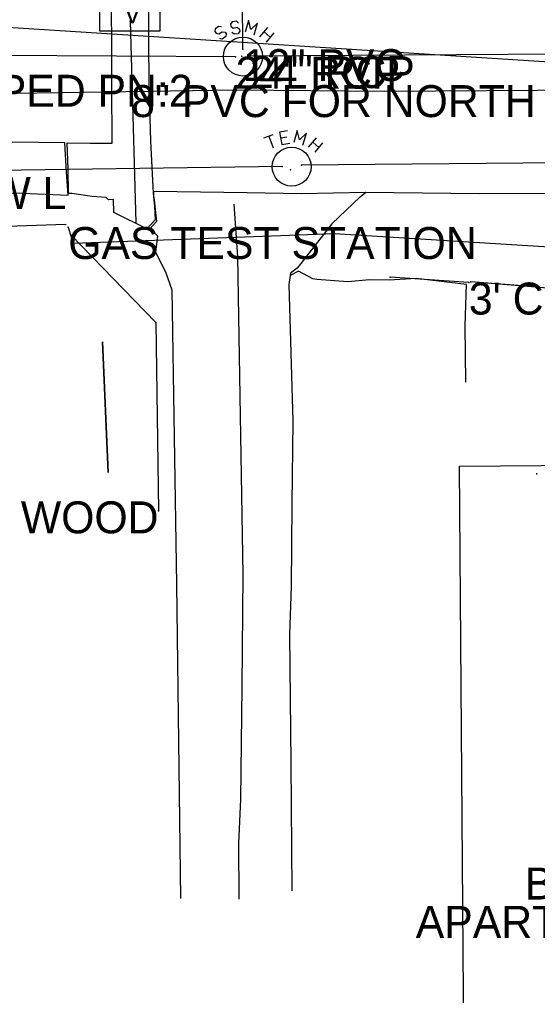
# Model space of a CAD drawing. Extents: x 1304270 to 1306561, y 1876019 to 1876752.
# Drawn here: x 1305592.5 to 1305673.5, y 1876265.9 to 1876418.6 of the extents above; entities that cross this region are included whole.
import ezdxf

# ---------------------------------------------------------------- set-up
doc = ezdxf.new("R2010")
doc.units = 0
for name, color, linetype in [('Default', 7, 'Continuous'), ('S_BUILDING', 7, 'Continuous'), ('S_BUILDING_ANNOT', 7, 'Continuous'), ('S_EDGE_CONCRETE', 7, 'Continuous'), ('S_EDGE_PAVEMENT', 7, 'Continuous'), ('S_ELECTRIC_UTILITIES_ANNOT', 7, 'Continuous'), ('S_FENCE', 7, 'Continuous'), ('S_FENCE_ANNOT', 7, 'Continuous'), ('S_FIBER_OPTIC_CABLE', 7, 'Continuous'), ('S_GAS_UTILITIES', 7, 'Continuous'), ('S_MISC_STRUCTURES_ANNOT', 7, 'Continuous'), ('S_MSC_PT_SYM', 7, 'Continuous'), ('S_PARKING', 7, 'Continuous'), ('S_PAVEMENT_CROWN', 7, 'Continuous'), ('S_PRIMARY_CTL_ANNOT', 7, 'Continuous'), ('S_SANITARY_SEWER', 7, 'Continuous'), ('S_SANITARY_SEWER_ANNOT', 7, 'Continuous'), ('S_STR_PT_SYM', 7, 'Continuous'), ('S_SURVEY_TEXT_ANNOT', 7, 'Continuous'), ('S_TELEPHONE_UTILITIES_ANNOT', 7, 'Continuous'), ('S_TREE', 7, 'Continuous'), ('S_UTL_PT_SYM', 7, 'Continuous'), ('S_WATER_UTILITIES', 7, 'Continuous')]:
    doc.layers.add(name, color=color, linetype=linetype)

msp = doc.modelspace()

# ---------------------------------------------------------------- linework, layer by layer
at = {"layer": 'Default'}
msp.add_line((1305473.53, 1876424.94), (1305993.25, 1876391.55), dxfattribs=at)
at = {"layer": 'S_BUILDING'}
msp.add_lwpolyline([(1305662.34, 1876217.81), (1305661.36, 1876348.7), (1305693.3, 1876348.94), (1305694.28, 1876218.05)], close=True, dxfattribs=at)
at = {"layer": 'S_EDGE_CONCRETE'}
for points in [[(1305600.18, 1876391.37), (1305600.11, 1876395.15), (1305599.99, 1876399.31), (1305603.58, 1876399.22), (1305607.04, 1876399.22), (1305606.97, 1876408.21), (1305606.95, 1876415.73), (1305606.84, 1876422.83)], [(1305612.7, 1876421.97), (1305612.68, 1876415.16), (1305612.77, 1876408.63), (1305613.02, 1876399.57), (1305613.37, 1876392.39), (1305613.42, 1876391.39), (1305613.66, 1876389.36), (1305613.74, 1876387.23), (1305612.42, 1876385.83), (1305607.29, 1876388.41), (1305607.23, 1876390.4), (1305606.42, 1876390.35), (1305606.05, 1876390.71), (1305603.89, 1876390.91), (1305600.7, 1876391.35)], [(1305587.07, 1876391.56), (1305592.92, 1876391.39), (1305600.11, 1876391.1), (1305599.86, 1876394.71), (1305599.63, 1876399.29), (1305591.28, 1876399.4), (1305587.25, 1876399.27), (1305587.19, 1876395.57), (1305587.04, 1876391.81)], [(1305600.7, 1876391.35), (1305600.18, 1876391.37)]]:
    msp.add_lwpolyline(points, dxfattribs=at)
at = {"layer": 'S_EDGE_PAVEMENT'}
for points in [[(1305613.53, 1876391.75), (1305628.13, 1876391.53), (1305636.57, 1876391.38), (1305646.7, 1876391.57), (1305664.4, 1876391.37), (1305677.09, 1876391.42), (1305689.77, 1876391.47), (1305705.71, 1876391.48), (1305716.06, 1876391.37), (1305738.42, 1876391.47), (1305752.22, 1876391.48), (1305766.03, 1876391.49), (1305779.83, 1876391.49), (1305793.63, 1876391.5), (1305816.58, 1876391.56), (1305839.54, 1876391.62), (1305862.15, 1876391.47), (1305884.77, 1876391.33), (1305898.76, 1876391.18), (1305901.73, 1876391.47), (1305913.59, 1876391.75), (1305924.92, 1876391.98), (1305934.98, 1876391.98)], [(1305613.54, 1876390.81), (1305613.53, 1876391.75)], [(1305645.8, 1876390.84), (1305646.7, 1876391.57)], [(1305613.54, 1876390.81), (1305613.95, 1876386.98), (1305612.91, 1876385.84), (1305613.43, 1876385.43), (1305614.1, 1876384.73), (1305613.77, 1876382.16), (1305615.36, 1876379.1), (1305616.36, 1876376.27), (1305616.71, 1876353.21), (1305617.06, 1876330.15), (1305617.38, 1876305.59), (1305617.7, 1876281.03)], [(1305645.8, 1876390.84), (1305641.39, 1876386.64), (1305635.93, 1876379.66), (1305634.93, 1876378.88), (1305634.67, 1876377.12), (1305635.26, 1876355.72), (1305635.13, 1876342.79), (1305635, 1876329.85), (1305634.78, 1876322.35), (1305634.95, 1876302.28), (1305635.12, 1876282.21)]]:
    msp.add_lwpolyline(points, dxfattribs=at)
at = {"layer": 'S_FENCE'}
for p, q in [((1305662.81, 1876377.42), (1305650.48, 1876378.27)), ((1305697.1, 1876374.76), (1305663.1, 1876377.56))]:
    msp.add_line(p, q, dxfattribs=at)
for points in [[(1305662.81, 1876377.42), (1305650.48, 1876378.27)], [(1305662.81, 1876377.42), (1305650.48, 1876378.27)], [(1305673.18, 1876376.73), (1305663.1, 1876377.56)], [(1305673.18, 1876376.73), (1305663.1, 1876377.56)]]:
    msp.add_lwpolyline(points, dxfattribs=at)
at = {"layer": 'S_FIBER_OPTIC_CABLE'}
for p, q in [((1305684.65, 1876396.24), (1305636.63, 1876395.82)), ((1305633.63, 1876395.59), (1305588.12, 1876394.97))]:
    msp.add_line(p, q, dxfattribs=at)
at = {"layer": 'S_GAS_UTILITIES'}
for p, q in [((1305599.74, 1876386.5), (1305541.16, 1876384.5)), ((1305600.99, 1876383.55), (1305600.25, 1876385.84)), ((1305600.56, 1876384.87), (1305613.85, 1876371.19)), ((1305641.77, 1876385.04), (1305600.99, 1876383.55)), ((1305681.24, 1876382.6), (1305641.77, 1876385.04)), ((1305613.85, 1876371.19), (1305614.27, 1876341.7))]:
    msp.add_line(p, q, dxfattribs=at)
at = {"layer": 'S_MSC_PT_SYM'}
for points in [[(1305609.97, 1876408.32), (1305609.97, 1876408.37), (1305609.97, 1876408.32), (1305609.92, 1876408.32), (1305609.97, 1876408.32), (1305609.97, 1876408.27), (1305609.97, 1876408.32), (1305610.02, 1876408.32)], [(1305600.14, 1876386.11), (1305600.14, 1876386.16), (1305600.14, 1876386.11), (1305600.09, 1876386.11), (1305600.14, 1876386.11), (1305600.14, 1876386.06), (1305600.14, 1876386.11), (1305600.19, 1876386.11)], [(1305650.48, 1876378.27), (1305650.48, 1876378.32), (1305650.48, 1876378.27), (1305650.43, 1876378.27), (1305650.48, 1876378.27), (1305650.48, 1876378.22), (1305650.48, 1876378.27), (1305650.53, 1876378.27)], [(1305662.81, 1876377.42), (1305662.81, 1876377.47), (1305662.81, 1876377.42), (1305662.76, 1876377.42), (1305662.81, 1876377.42), (1305662.81, 1876377.37), (1305662.81, 1876377.42), (1305662.86, 1876377.42)], [(1305663.1, 1876377.56), (1305663.1, 1876377.61), (1305663.1, 1876377.56), (1305663.05, 1876377.56), (1305663.1, 1876377.56), (1305663.1, 1876377.51), (1305663.1, 1876377.56), (1305663.15, 1876377.56)]]:
    msp.add_lwpolyline(points, dxfattribs=at)
at = {"layer": 'S_PARKING'}
msp.add_lwpolyline([(1305662.32, 1876361.82), (1305662.23, 1876370.65), (1305662.45, 1876377.11), (1305654.57, 1876378.06), (1305650.33, 1876377.81), (1305647.29, 1876377.87), (1305643.87, 1876377.56), (1305639.01, 1876377.9), (1305638.39, 1876378), (1305636.15, 1876379.23), (1305634.94, 1876378.6)], dxfattribs=at)
at = {"layer": 'S_PAVEMENT_CROWN'}
for points in [[(1305584.78, 1876406.94), (1305605.66, 1876407.25), (1305626.54, 1876407.56), (1305649.67, 1876407.38), (1305673.56, 1876407.51), (1305697.46, 1876407.64), (1305720.67, 1876407.97), (1305743.89, 1876408.29), (1305756.53, 1876408.46), (1305769.18, 1876408.63), (1305781.82, 1876408.79), (1305794.47, 1876408.96), (1305817.8, 1876409.07)], [(1305626.06, 1876389.71), (1305626.63, 1876381.43), (1305627.05, 1876356.58), (1305627.46, 1876331.74), (1305627.28, 1876314.17), (1305627.09, 1876296.6), (1305626.79, 1876289.63), (1305626.83, 1876280.91)]]:
    msp.add_lwpolyline(points, dxfattribs=at)
at = {"layer": 'S_SANITARY_SEWER'}
for p, q in [((1305627.46, 1876413.95), (1305625.83, 1876600.63)), ((1305623.69, 1876417.49), (1305623.15, 1876417.11)), ((1305624.11, 1876417.42), (1305623.69, 1876417.49)), ((1305623.15, 1876417.11), (1305623.07, 1876416.72)), ((1305623.07, 1876416.72), (1305623.26, 1876416.45)), ((1305623.26, 1876416.45), (1305623.69, 1876416.33)), ((1305623.69, 1876416.33), (1305624.23, 1876416.68)), ((1305624.23, 1876416.68), (1305624.7, 1876416.6)), ((1305624.77, 1876415.91), (1305624.23, 1876415.52)), ((1305624.7, 1876416.6), (1305624.85, 1876416.33)), ((1305624.85, 1876416.33), (1305624.77, 1876415.91)), ((1305630.12, 1876415.87), (1305631.36, 1876417.34)), ((1305630.78, 1876416.64), (1305631.75, 1876415.83)), ((1305632.33, 1876416.53), (1305631.09, 1876415.05)), ((1305624.23, 1876415.52), (1305623.84, 1876415.6)), ((1305931.77, 1876414.75), (1305628.57, 1876412.86)), ((1305626.32, 1876412.77), (1305348.54, 1876414.26))]:
    msp.add_line(p, q, dxfattribs=at)
for points in [[(1305626.79, 1876418.04), (1305626.44, 1876418.31), (1305625.78, 1876418.23), (1305625.55, 1876417.88), (1305625.59, 1876417.57), (1305625.94, 1876417.26), (1305626.56, 1876417.38), (1305626.94, 1876417.07), (1305626.98, 1876416.76), (1305626.71, 1876416.37), (1305626.09, 1876416.29), (1305625.74, 1876416.56)], [(1305629.23, 1876416.18), (1305629.77, 1876418.04), (1305628.73, 1876417.03), (1305628.34, 1876418.46), (1305627.8, 1876416.6)]]:
    msp.add_lwpolyline(points, dxfattribs=at)
msp.add_circle((1305627.47, 1876412.8), 3.05, dxfattribs=at)
at = {"layer": 'S_STR_PT_SYM'}
msp.add_lwpolyline([(1305673.46, 1876347.5), (1305673.46, 1876347.55), (1305673.46, 1876347.5), (1305673.41, 1876347.5), (1305673.46, 1876347.5), (1305673.46, 1876347.45), (1305673.46, 1876347.5), (1305673.51, 1876347.5)], dxfattribs=at)
at = {"layer": 'S_TELEPHONE_UTILITIES_ANNOT'}
for p, q in [((1305634.44, 1876401.18), (1305633.2, 1876400.94)), ((1305633.2, 1876400.94), (1305633.55, 1876399.05)), ((1305630.76, 1876400.05), (1305632.19, 1876400.6)), ((1305631.5, 1876400.36), (1305632.19, 1876398.5)), ((1305634.32, 1876400.17), (1305633.39, 1876400.01)), ((1305633.55, 1876399.05), (1305634.79, 1876399.24)), ((1305637.73, 1876398.62), (1305638.97, 1876400.09)), ((1305638.39, 1876399.39), (1305639.36, 1876398.58)), ((1305639.94, 1876399.28), (1305638.7, 1876397.81))]:
    msp.add_line(p, q, dxfattribs=at)
msp.add_lwpolyline([(1305636.84, 1876398.93), (1305637.39, 1876400.79), (1305636.34, 1876399.78), (1305635.95, 1876401.22), (1305635.41, 1876399.36)], dxfattribs=at)
msp.add_circle((1305635.09, 1876395.56), 3.05, dxfattribs=at)
at = {"layer": 'S_TREE'}
for points in [[(1305606.39, 1876347.7), (1305605.48, 1876368.15)], [(1305605.48, 1876368.15), (1305606.39, 1876347.7)]]:
    msp.add_lwpolyline(points, dxfattribs=at)
at = {"layer": 'S_UTL_PT_SYM'}
for points in [[(1305609.84, 1876418.34), (1305609.84, 1876418.39), (1305609.84, 1876418.34), (1305609.79, 1876418.34), (1305609.84, 1876418.34), (1305609.84, 1876418.29), (1305609.84, 1876418.34), (1305609.89, 1876418.34)], [(1305626.32, 1876412.77), (1305626.32, 1876412.82), (1305626.32, 1876412.77), (1305626.27, 1876412.77), (1305626.32, 1876412.77), (1305626.32, 1876412.72), (1305626.32, 1876412.77), (1305626.37, 1876412.77)], [(1305627.32, 1876412.83), (1305627.32, 1876412.88), (1305627.32, 1876412.83), (1305627.27, 1876412.83), (1305627.32, 1876412.83), (1305627.32, 1876412.78), (1305627.32, 1876412.83), (1305627.37, 1876412.83)], [(1305627.46, 1876413.95), (1305627.46, 1876414), (1305627.46, 1876413.95), (1305627.41, 1876413.95), (1305627.46, 1876413.95), (1305627.46, 1876413.9), (1305627.46, 1876413.95), (1305627.51, 1876413.95)], [(1305628.57, 1876412.86), (1305628.57, 1876412.91), (1305628.57, 1876412.86), (1305628.52, 1876412.86), (1305628.57, 1876412.86), (1305628.57, 1876412.81), (1305628.57, 1876412.86), (1305628.62, 1876412.86)], [(1305633.63, 1876395.59), (1305633.63, 1876395.64), (1305633.63, 1876395.59), (1305633.58, 1876395.59), (1305633.63, 1876395.59), (1305633.63, 1876395.54), (1305633.63, 1876395.59), (1305633.68, 1876395.59)], [(1305634.9, 1876395.09), (1305634.9, 1876395.14), (1305634.9, 1876395.09), (1305634.85, 1876395.09), (1305634.9, 1876395.09), (1305634.9, 1876395.04), (1305634.9, 1876395.09), (1305634.95, 1876395.09)], [(1305636.63, 1876395.82), (1305636.63, 1876395.87), (1305636.63, 1876395.82), (1305636.58, 1876395.82), (1305636.63, 1876395.82), (1305636.63, 1876395.77), (1305636.63, 1876395.82), (1305636.68, 1876395.82)], [(1305610.73, 1876386.8), (1305610.73, 1876386.85), (1305610.73, 1876386.8), (1305610.68, 1876386.8), (1305610.73, 1876386.8), (1305610.73, 1876386.75), (1305610.73, 1876386.8), (1305610.78, 1876386.8)], [(1305599.74, 1876386.5), (1305599.74, 1876386.55), (1305599.74, 1876386.5), (1305599.69, 1876386.5), (1305599.74, 1876386.5), (1305599.74, 1876386.45), (1305599.74, 1876386.5), (1305599.79, 1876386.5)], [(1305600.25, 1876385.84), (1305600.25, 1876385.89), (1305600.25, 1876385.84), (1305600.2, 1876385.84), (1305600.25, 1876385.84), (1305600.25, 1876385.79), (1305600.25, 1876385.84), (1305600.3, 1876385.84)], [(1305600.56, 1876384.87), (1305600.56, 1876384.92), (1305600.56, 1876384.87), (1305600.51, 1876384.87), (1305600.56, 1876384.87), (1305600.56, 1876384.82), (1305600.56, 1876384.87), (1305600.61, 1876384.87)], [(1305641.77, 1876385.04), (1305641.77, 1876385.09), (1305641.77, 1876385.04), (1305641.72, 1876385.04), (1305641.77, 1876385.04), (1305641.77, 1876384.99), (1305641.77, 1876385.04), (1305641.82, 1876385.04)], [(1305600.99, 1876383.55), (1305600.99, 1876383.6), (1305600.99, 1876383.55), (1305600.94, 1876383.55), (1305600.99, 1876383.55), (1305600.99, 1876383.5), (1305600.99, 1876383.55), (1305601.04, 1876383.55)], [(1305613.85, 1876371.19), (1305613.85, 1876371.24), (1305613.85, 1876371.19), (1305613.8, 1876371.19), (1305613.85, 1876371.19), (1305613.85, 1876371.14), (1305613.85, 1876371.19), (1305613.9, 1876371.19)], [(1305614.27, 1876341.7), (1305614.27, 1876341.75), (1305614.27, 1876341.7), (1305614.22, 1876341.7), (1305614.27, 1876341.7), (1305614.27, 1876341.65), (1305614.27, 1876341.7), (1305614.32, 1876341.7)]]:
    msp.add_lwpolyline(points, dxfattribs=at)
at = {"layer": 'S_WATER_UTILITIES'}
for p, q in [((1305605.07, 1876416.79), (1305605.07, 1876426.2)), ((1305614.48, 1876426.2), (1305614.48, 1876416.79)), ((1305609.84, 1876418.34), (1305610.73, 1876386.8)), ((1305614.48, 1876416.79), (1305605.07, 1876416.79))]:
    msp.add_line(p, q, dxfattribs=at)

# ---------------------------------------------------------------- texts
at = {"layer": 'S_BUILDING_ANNOT'}
for s, p in [('1 STRY WOOD', (1305567.46, 1876338.18)), ('B/F', (1305671.58, 1876280.87)), ('APARTMENTS', (1305654.51, 1876274.87))]:
    msp.add_text(s, height=5, dxfattribs=at).set_placement(p)
at = {"layer": 'S_ELECTRIC_UTILITIES_ANNOT'}
msp.add_text('POINT ON ROAD UNDER LOW L', height=5, dxfattribs=at).set_placement((1305498.07, 1876388.92))
at = {"layer": 'S_FENCE_ANNOT'}
msp.add_text("3' CHAINLINK/MTL POST GOOD", height=5, dxfattribs=at).set_placement((1305662.81, 1876372.42))
at = {"layer": 'S_MISC_STRUCTURES_ANNOT'}
msp.add_text('GAS TEST STATION', height=5, dxfattribs=at).set_placement((1305600.14, 1876381.11))
at = {"layer": 'S_PRIMARY_CTL_ANNOT'}
msp.add_text('PD:AHTD STD. MONUMENT STAMPED PN:2', height=5, dxfattribs=at).set_placement((1305481.03, 1876404.94))
at = {"layer": 'S_SANITARY_SEWER_ANNOT'}
for s, p in [('24" RCP', (1305626.32, 1876407.77)), ('12" PVC', (1305627.46, 1876408.95)), ('24" RCP', (1305628.57, 1876407.86))]:
    msp.add_text(s, height=5, dxfattribs=at).set_placement(p)
at = {"layer": 'S_SURVEY_TEXT_ANNOT'}
msp.add_text('8" PVC FOR NORTH SOUTH', height=5, dxfattribs=at).set_placement((1305609.97, 1876403.32))
at = {"layer": 'S_WATER_UTILITIES'}
msp.add_text('V', height=3, rotation=360, dxfattribs=at).set_placement((1305608.85, 1876417.98))

doc.saveas('drawing.dxf')
